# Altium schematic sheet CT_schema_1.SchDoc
size 499 x 466 mm
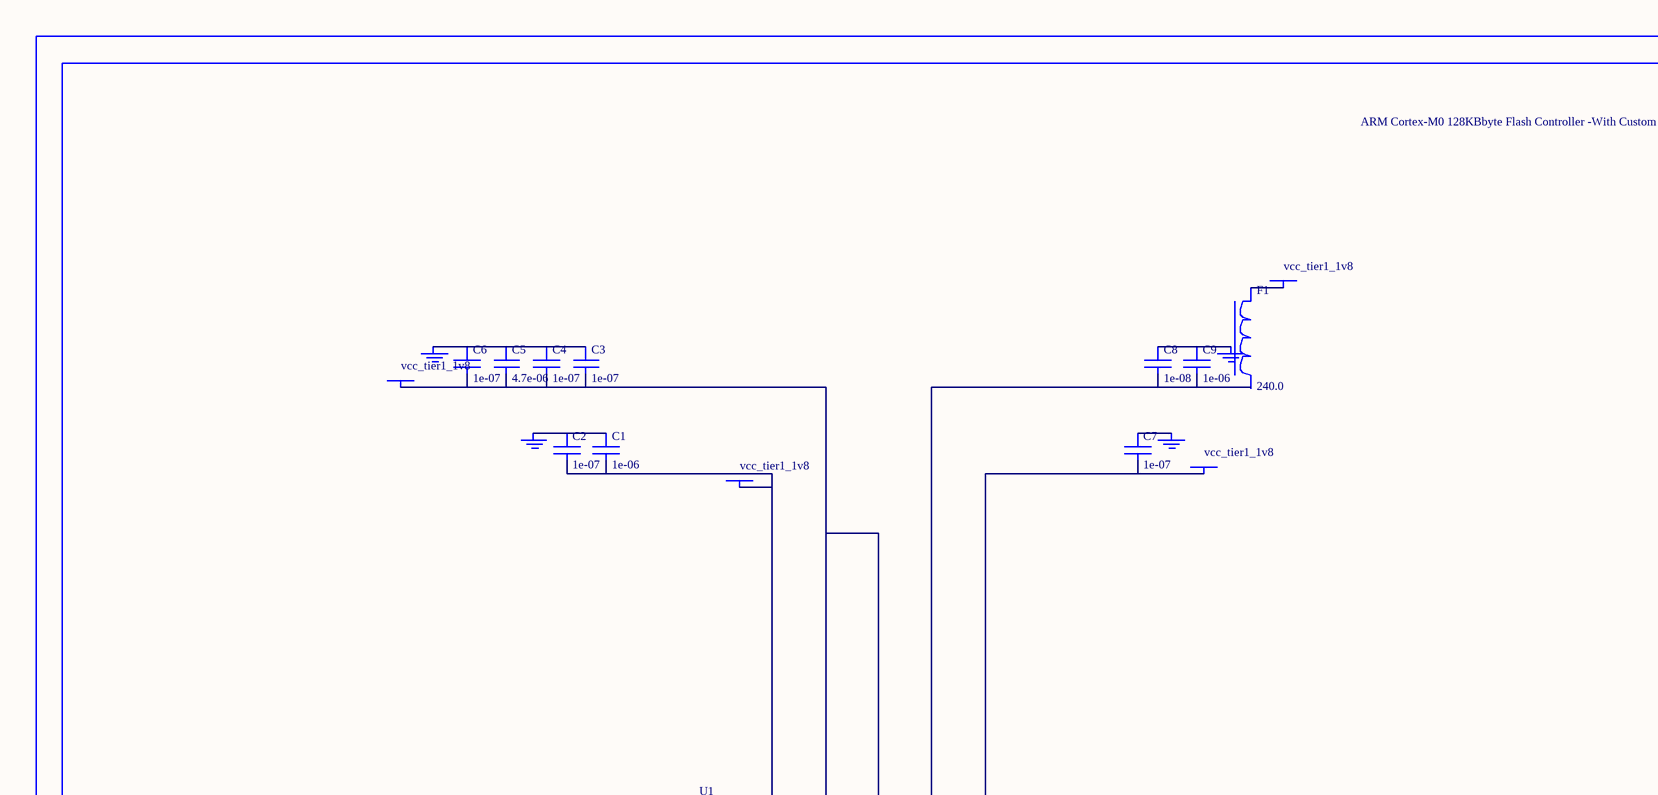
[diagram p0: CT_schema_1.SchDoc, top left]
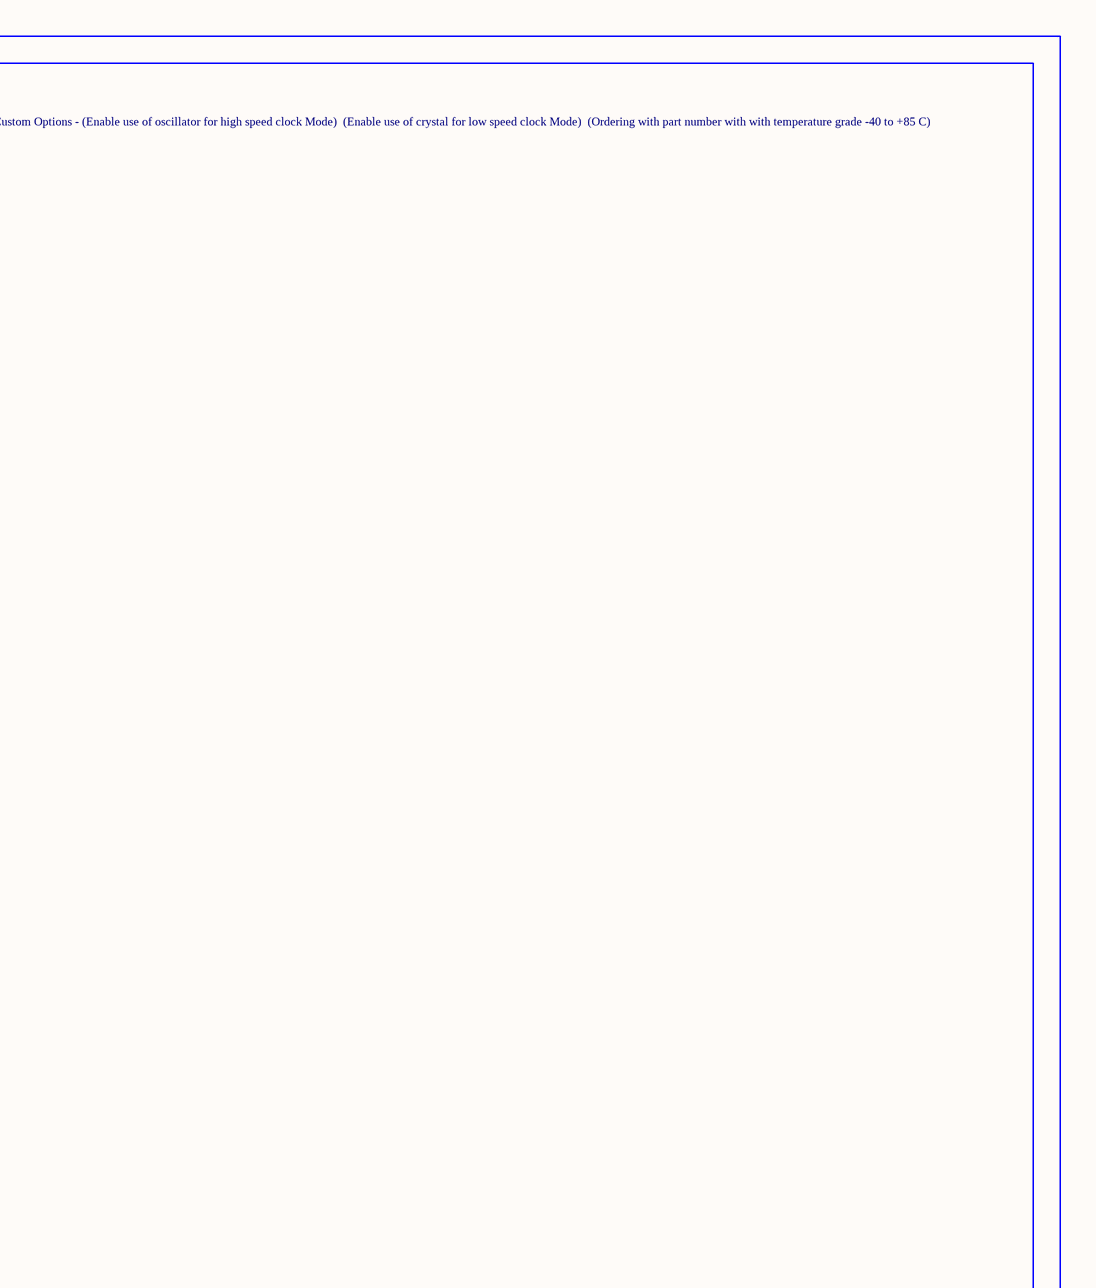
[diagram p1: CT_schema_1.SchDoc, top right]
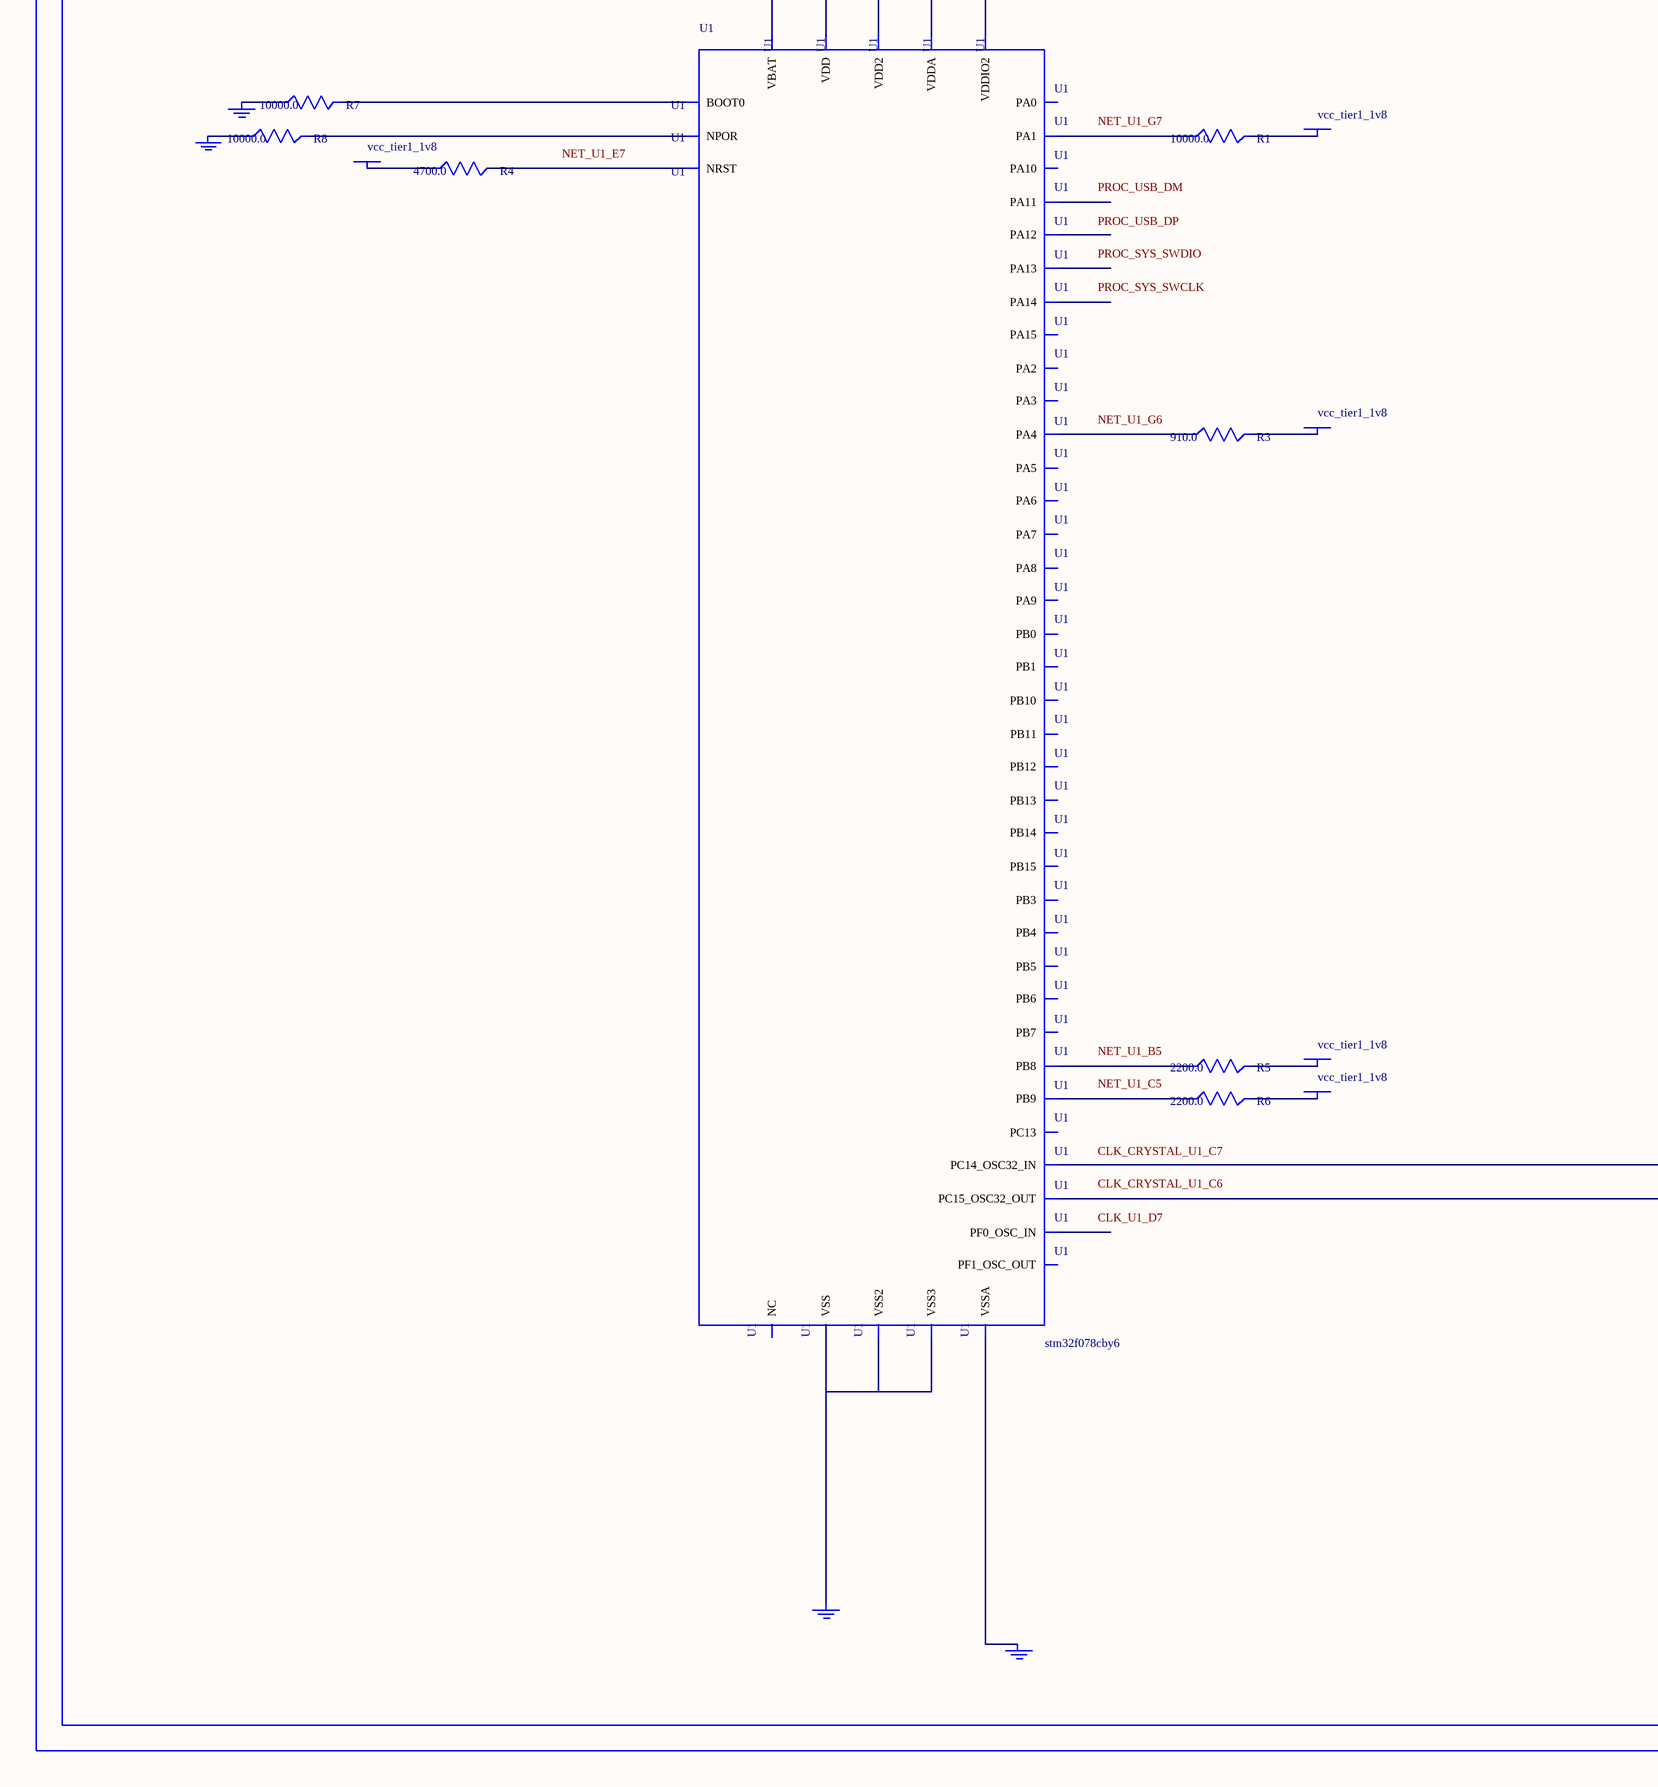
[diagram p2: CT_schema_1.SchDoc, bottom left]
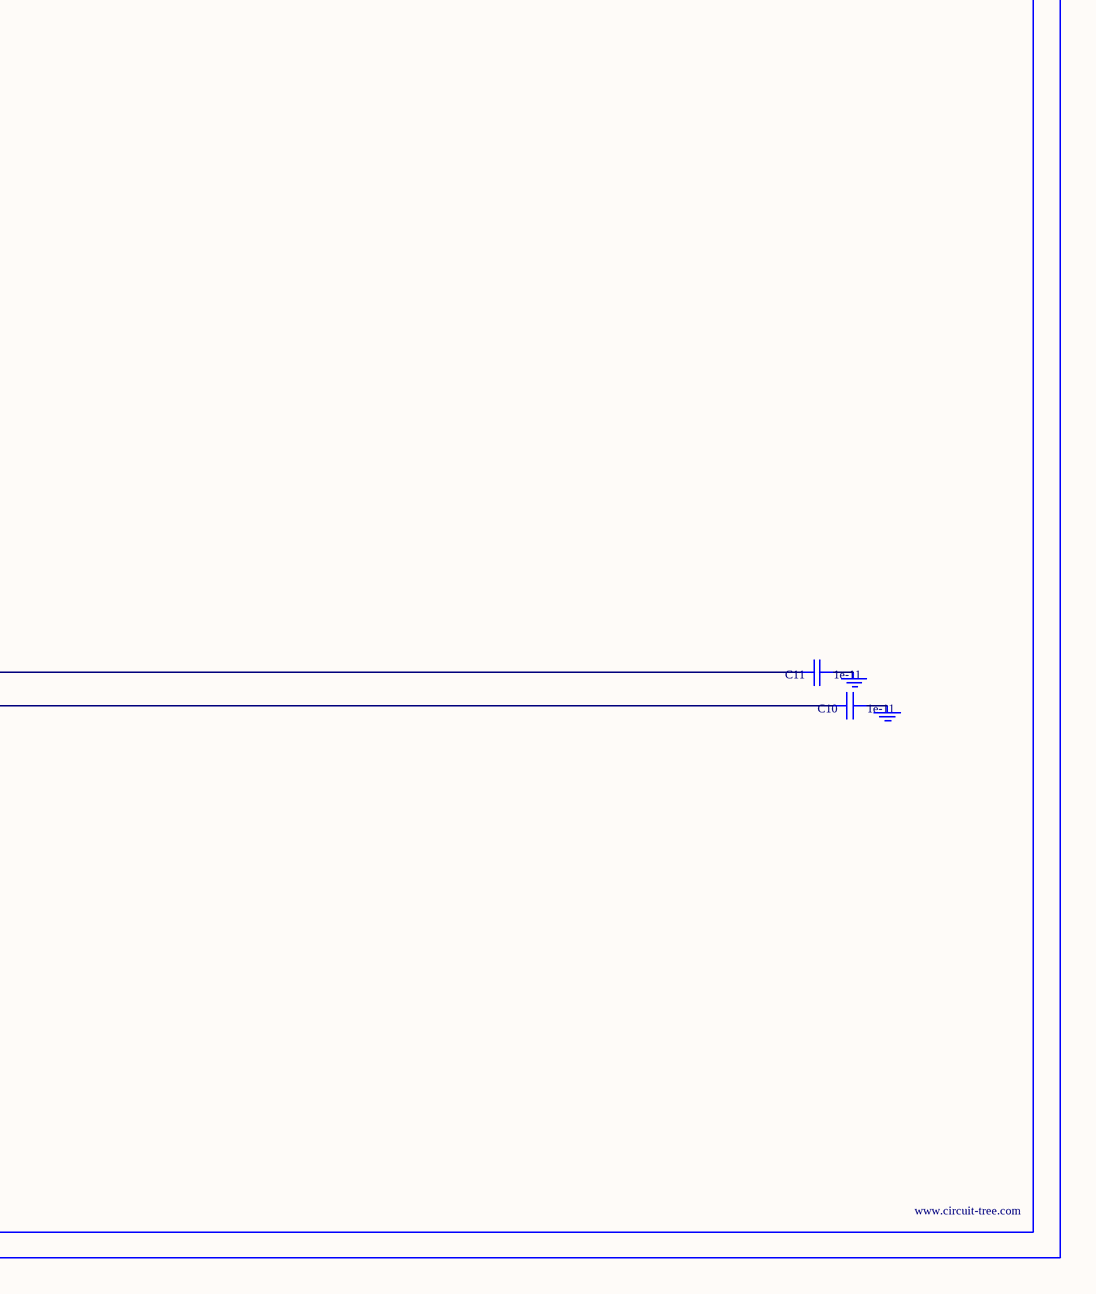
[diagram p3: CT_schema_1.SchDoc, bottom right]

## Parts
BORDER0  (no value)
C1  1e-06  [C0603]
C2  1e-07  [C0603]
C3  1e-07  [C0603]
C4  1e-07  [C0603]
C5  4.7e-06  [C0603]
C6  1e-07  [C0603]
C7  1e-07  [C0603]
C8  1e-08  [C0603]
C9  1e-06  [C0603]
C10  1e-11  [C0402]
C11  1e-11  [C0402]
F1  240.0  [L0603]
GND_INSTANCE_0_0  (no value)
GND_INSTANCE_0_1  (no value)
GND_INSTANCE_0_2  (no value)
GND_INSTANCE_0_3  (no value)
GND_INSTANCE_0_4  (no value)
GND_INSTANCE_0_5  (no value)
GND_INSTANCE_0_6  (no value)
GND_INSTANCE_0_7  (no value)
GND_INSTANCE_0_8  (no value)
GND_INSTANCE_0_9  (no value)
POWER_INSTANCE_0_0  vcc_tier1_1v8
POWER_INSTANCE_0_1  vcc_tier1_1v8
POWER_INSTANCE_0_2  vcc_tier1_1v8
POWER_INSTANCE_0_3  vcc_tier1_1v8
POWER_INSTANCE_0_4  vcc_tier1_1v8
POWER_INSTANCE_0_5  vcc_tier1_1v8
POWER_INSTANCE_0_6  vcc_tier1_1v8
POWER_INSTANCE_0_7  vcc_tier1_1v8
POWER_INSTANCE_0_8  vcc_tier1_1v8
R1  10000.0  [R0603]
R3  910.0  [R0603]
R4  4700.0  [R0603]
R5  2200.0  [R0603]
R6  2200.0  [R0603]
R7  10000.0  [R0603]
R8  10000.0  [R0603]
U1  stm32f078cby6  [WLCSP49]

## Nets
NetC1_1: C1.1 C2.1 GND_INSTANCE_0_0.0(GND)
NetC1_2: C1.2 C2.2 POWER_INSTANCE_0_0.0(PWR) U1.B7(VBAT)
NetC3_1: C3.1 C4.1 C5.1 C6.1 GND_INSTANCE_0_2.0(GND)
NetC3_2: C3.2 C4.2 C5.2 C6.2 POWER_INSTANCE_0_2.0(PWR) U1.A7(VDD) U1.F2(VDD2)
NetC7_1: C7.1 GND_INSTANCE_0_3.0(GND)
NetC7_2: C7.2 POWER_INSTANCE_0_3.0(PWR) U1.B2(VDDIO2)
NetC8_1: C8.1 C9.1 GND_INSTANCE_0_1.0(GND)
NetC8_2: C8.2 C9.2 U1.F7(VDDA)
NetC10_1: C10.1 GND_INSTANCE_0_6.0(GND)
NetC10_2: C10.2 U1.C6(PC15_OSC32_OUT)
NetC11_1: C11.1 GND_INSTANCE_0_7.0(GND)
NetC11_2: C11.2 U1.C7(PC14_OSC32_IN)
NetF1_1: F1.1 POWER_INSTANCE_0_1.0(PWR)
NetGND_INSTANCE_0_4_0: GND_INSTANCE_0_4.0(GND) R7.1
NetGND_INSTANCE_0_5_0: GND_INSTANCE_0_5.0(GND) R8.1
NetGND_INSTANCE_0_8_0: GND_INSTANCE_0_8.0(GND) U1.E6(VSSA)
NetGND_INSTANCE_0_9_0: GND_INSTANCE_0_9.0(GND) U1.A6(VSS) U1.B1(VSS2) U1.D3(VSS3)
NetPOWER_INSTANCE_0_4_0: POWER_INSTANCE_0_4.0(PWR) R4.1
NetPOWER_INSTANCE_0_5_0: POWER_INSTANCE_0_5.0(PWR) R1.2
NetPOWER_INSTANCE_0_6_0: POWER_INSTANCE_0_6.0(PWR) R3.2
NetPOWER_INSTANCE_0_7_0: POWER_INSTANCE_0_7.0(PWR) R5.2
NetPOWER_INSTANCE_0_8_0: POWER_INSTANCE_0_8.0(PWR) R6.2
NetR1_1: R1.1 U1.G7(PA1)
NetR3_1: R3.1 U1.G6(PA4)
NetR4_2: R4.2 U1.E7(NRST)
NetR5_1: R5.1 U1.B5(PB8)
NetR6_1: R6.1 U1.C5(PB9)
NetR7_2: R7.2 U1.A5(BOOT0)
NetR8_2: R8.2 U1.G3(NPOR)

Not connected (* = marked no-connect by the designer): F1 2; U1 A1(PA14) A2(PA15) A3(PB3) A4(PB4) B3(PA13) B4(PB5) B6(NC) C1(PA11) C2(PA10) C3(PA12) C4(PB6) D1(PA8) D2(PA9) D4(PB7) D5(PC13) D6(PF1_OSC_OUT) D7(PF0_OSC_IN) E1(PB15) E2(PB12) E3(PB10) E4(PA3) E5(PA2) F1(PB14) F3(PA7) F4(PA6) F5(PA5) F6(PA0) G1(PB13) G2(PB11) G4(PB1) G5(PB0)

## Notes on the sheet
- Labels drawn without touching a wire or pin: CLK_CRYSTAL_U1_C6, CLK_CRYSTAL_U1_C7, CLK_U1_D7, NET_U1_B5, NET_U1_C5, NET_U1_E7, NET_U1_G6, NET_U1_G7, PROC_SYS_SWCLK, PROC_SYS_SWDIO, PROC_USB_DM, PROC_USB_DP

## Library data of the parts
BORDER0 = BORDER_PAGE0
C1 C9 = C0603C105K3RACTU
C2-C4 C6 C7 = 06035C104K4Z2A
C5 = GRM188R6YA475KE15D
C8 = 06035C103K4Z2A
C10 C11 = C0402C100K3GACTU
F1 = Z0603C241ASMST
GND_INSTANCE_0_0-GND_INSTANCE_0_9 = GND
POWER_INSTANCE_0_0-POWER_INSTANCE_0_8 = PWR
R1 R7 R8 = RC0603JR-0710KL
R3 = RC0603JR-07910RL
R4 = RC0603JR-074K7L
R5 R6 = RC0603JR-072K2L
